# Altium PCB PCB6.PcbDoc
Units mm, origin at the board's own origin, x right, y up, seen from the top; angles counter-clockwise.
Board outline 26 x 20 mm, 2 copper layers (Top Layer, Bottom Layer); 9 components, 18 nets, 52 pads, 1 vias.
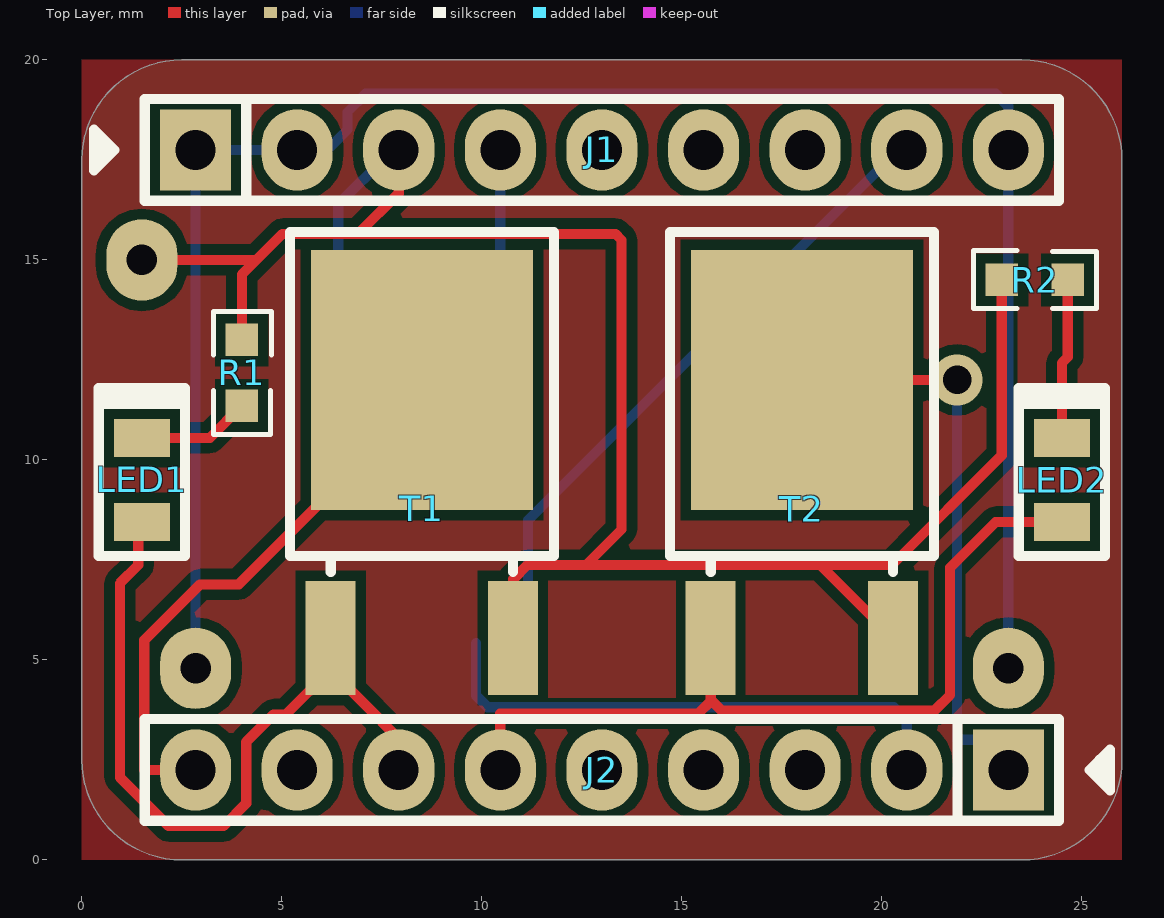
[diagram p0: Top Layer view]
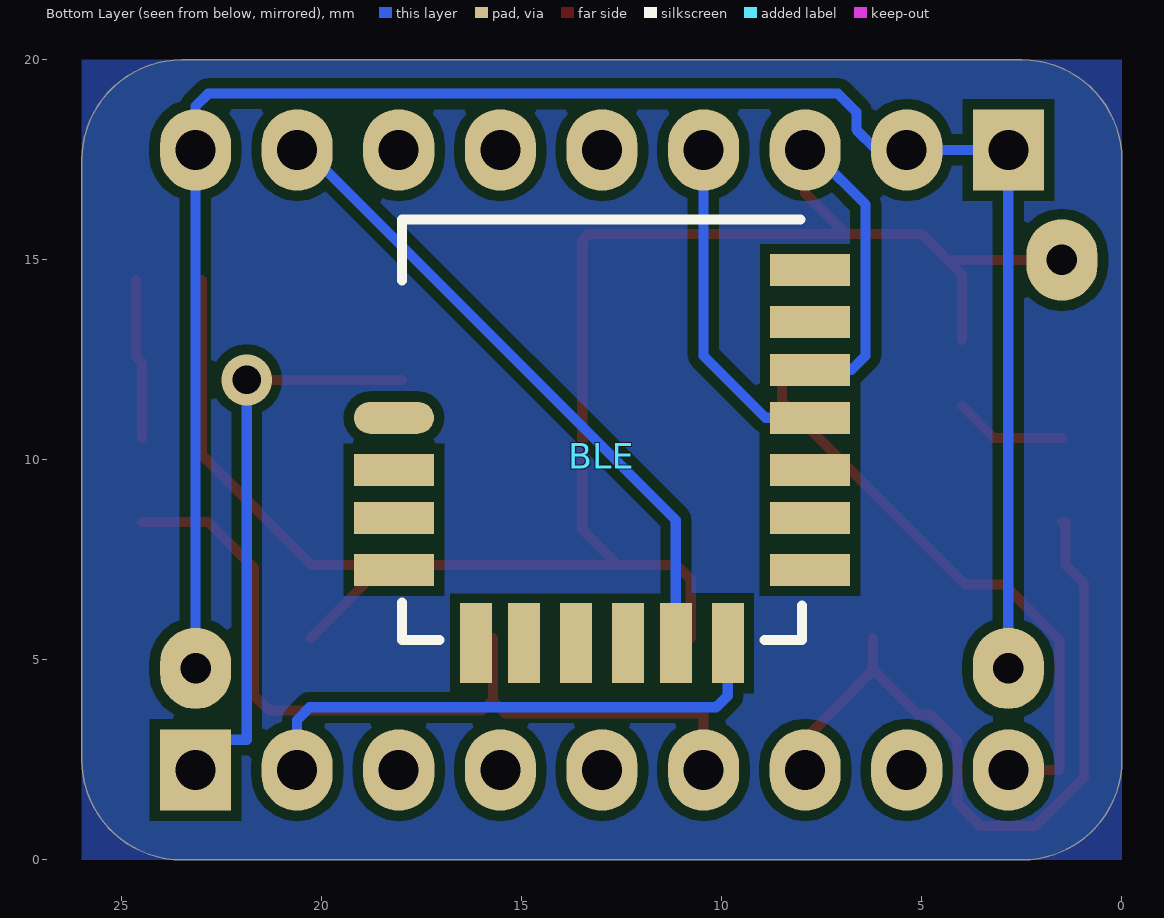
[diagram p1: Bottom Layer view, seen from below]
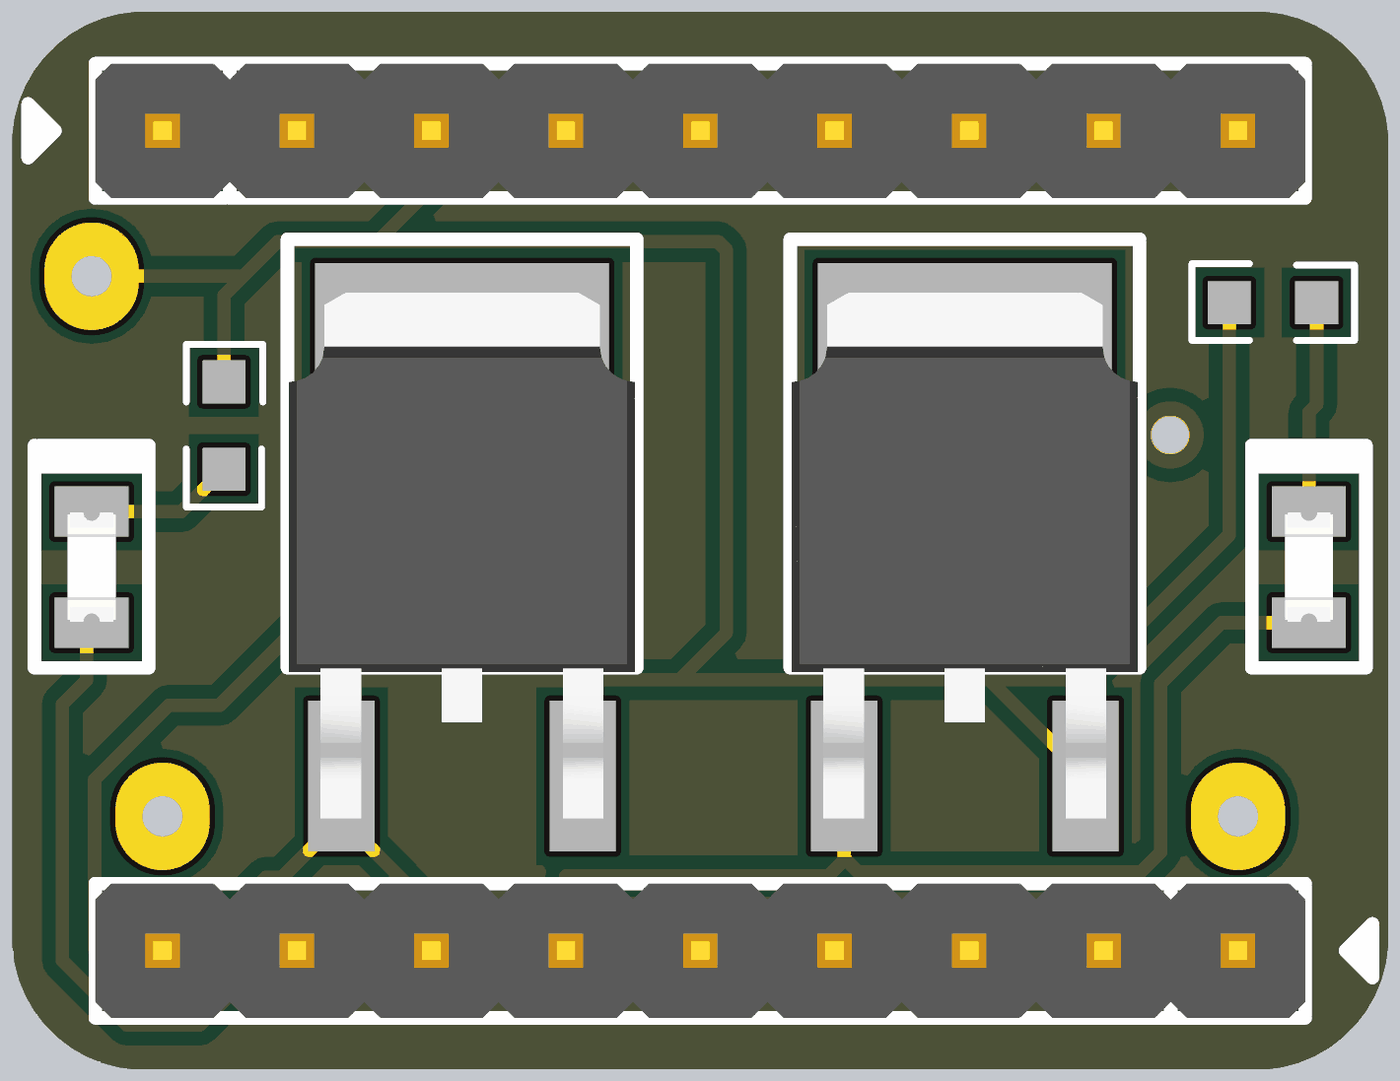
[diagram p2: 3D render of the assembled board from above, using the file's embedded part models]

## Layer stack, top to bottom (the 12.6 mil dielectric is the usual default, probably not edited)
Top Solder: solder mask 0.0102, Solder Resist, Dk 3.5
Top Layer: signal copper 0.0356
Dielectric 1: dielectric 0.32, FR-4, Dk 4.8
Bottom Layer: signal copper 0.0356
Bottom Solder: solder mask 0.0102, Solder Resist, Dk 3.5

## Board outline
0,2.5 ccw(c2.5,2.5) 2.5,0 23.5,0 ccw(c23.5,2.5) 26,2.5 26,17.5 ccw(c23.5,17.5) 23.5,20 2.5,20 ccw(c2.5,17.5) 0,17.5

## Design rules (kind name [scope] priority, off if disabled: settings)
Clearance [All] p1: gap=0.254
PolygonConnect [All] p1: connectstyle=Relief reliefconductorwidth=0.254 reliefentries=4 polygonreliefangle="90 Angle" airgapwidth=0.254
RoutingVias [All] p1: holewidth=0.711 width=1.27 viastyle="Through Hole" minholewidth=0.711 minwidth=1.27 maxholewidth=0.711 maxwidth=1.27
SolderMaskExpansion [All] p1: expansion=0.102
Width [All] p1: maxlimit=0.254 minlimit=0.254 preferedwidth=0.254
29 further rules are at their usual default settings.

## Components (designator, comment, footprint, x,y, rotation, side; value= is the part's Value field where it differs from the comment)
BLE "WH-BLE103" PCBComponent_1 18,5.5 r180 bottom
J1 "HDR1x9" PIN-9-2.54-1.0 13,17.75 r0 top
J2 "HDR1x9" PIN-9-2.54-1.0 13,2.25 r180 top
LED1 "LED" LED-0805 1.5,9.5 r90 top
LED2 "LED" LED-0805 24.5,9.5 r90 top
R1 "Res2" 0603 4,13 r270 top
R2 "Res2" 0603 23,14.5 r0 top
T1 "BT136S-600E" TO-252 8.5,12 r0 top
T2 "BT136S-600E" TO-252 18,12 r0 top

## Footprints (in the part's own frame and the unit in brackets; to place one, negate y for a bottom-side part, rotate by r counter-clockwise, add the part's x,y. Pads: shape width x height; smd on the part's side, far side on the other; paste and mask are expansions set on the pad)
0603 [mil]
  rect 32x32 smd: 1(-0.16,-0.01) 2(64.84,-0.01)
  silkscreen extent -28,-28 93,29
LED-0805 [mm] "LED, SMD, 0805"
  rect 0.95x1.4 smd: 1(-1.05,0) 2(1.05,0)
  silkscreen extent -1.9,-1.08 2.3,1.08, body extent -1.03,-0.46 1.03,0.45, height 0.85
PCBComponent_1 [mm]
  oval 2x0.8 smd: 1(-0.2,5.554)
  rect 2x0.8 smd: 2(-0.2,4.254) 3(-0.2,3.054) 4(-0.2,1.754) 11(10.2,1.754) 12(10.2,3.054) 13(10.2,4.254) 14(10.2,5.554) 15(10.2,6.754) 16(10.2,7.954) 17(10.2,9.254)
  rect 0.8x2 smd: 5(1.846,-0.082) 6(3.046,-0.082) 7(4.346,-0.082) 8(5.646,-0.082) 9(6.846,-0.082) 10(8.146,-0.082)
  silkscreen extent 0,0 10,10.51
PIN-9-2.54-1.0 [mil] "Pin Header"
  rect 70x80 hole 39.37: 1(-400,0)
  oval 70x80 hole 39.37: 2(-300,0) 3(-200,0) 4(-100,0) 5(0,0) 6(100,0) 7(200,0) 8(300,0) 9(400,0)
  silkscreen extent -500,-50 450,50, body extent -450,-50 450,50, height 398
TO-252 [mm] "TO-252, DPAK"
  rect 1.25x2.85 smd: 1(-2.28,-6.45) 3(2.28,-6.45)
  rect 5.55x6.5 smd: 4(0,0)
  silkscreen extent -3.3,-4.8 3.3,3.7, body extent -3.27,-7.25 3.27,2.69, height 2.41

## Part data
J1 J2: "Connector"
R1 R2: "Resistor"
T1 T2: "Triac"

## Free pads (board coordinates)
  oval 1.778x2.032 hole 0.762: 3(1.5,15) 3(2.84,4.79) 3(23.16,4.79)

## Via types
v1: diameter 1.27, hole 0.711, Top Layer to Bottom Layer, tented both sides, 1 vias

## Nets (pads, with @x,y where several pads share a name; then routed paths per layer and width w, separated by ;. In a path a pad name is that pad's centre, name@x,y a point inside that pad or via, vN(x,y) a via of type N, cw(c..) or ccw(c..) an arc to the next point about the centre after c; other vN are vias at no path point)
3.3V: BLE.14 J1.4 | length 8.4
  Bottom Layer w0.254: BLE.14 8.91,11.054 10.46,12.604 J1.4
5V: J1.1 J1.2 J1.9 | length 22.4
  Bottom Layer w0.254: J1.1 J1.2 6.131,17.75 6.639,18.258 6.639,18.7 7.096,19.157 22.844,19.157 23.16,18.841 J1.9
A1: J2.9 T1.4 | length 14.5
  Top Layer w0.254: J2.9 1.559,2.25 1.559,5.492 2.956,6.889 3.921,6.889 8.5,11.468 T1.4
A2: J2.1 T2.4 | length 14.9
  Top Layer w0.254: T2.4 v1(21.879,12)
  Bottom Layer w0.254: v1(21.879,12) 21.879,3.003 23.16,3.003 J2.1
CON0: J2.8
CON1: J2.7 LED1.1 T1.1 | length 19
  Top Layer w0.254: LED1.1 1.406,8.45 1.406,7.372 0.949,6.914 0.949,2.063 2.168,0.844 3.54,0.844 4.11,1.414 4.11,2.952 4.796,3.638 5.102,3.638 T1.1@6.22,4.755 ; T1.1 T1.1@6.22,4.755 ; J2.7 7.92,3.028 T1.1@6.22,4.755
CON2: J2.6 LED2.1 T2.1 | length 21.1
  Top Layer w0.254: J2.6 10.46,3.663 15.415,3.663 15.72,3.968 15.72,4.005 ; T2.1 15.72,4.005 ; LED2.1 22.844,8.45 21.701,7.307 21.701,4.12 21.32,3.739 15.986,3.739 15.72,4.005
CON3: J2.5
CON4: J1.5
CON5: J1.6
GND: BLE.15 J1.3 R1.1 R2.1 T1.3 T2.3 | length 52
  Top Layer w0.254: R1.1 4,14.636 5.016,15.652 6.904,15.652 ; J1.3 7.92,16.668 6.904,15.652 ; T1.3 10.78,7.016 11.136,7.372 12.602,7.372 ; T2.3 18.458,7.372 ; R2.1 22.996,10.114 20.253,7.372 18.458,7.372 ; 6.904,15.652 13.338,15.652 13.49,15.5 13.49,8.26 12.602,7.372 ; 12.602,7.372 18.458,7.372
  Bottom Layer w0.254: BLE.15 6.76,12.254 6.41,12.604 6.41,16.389 7.629,17.608 7.92,17.608 J1.3
NetLED1_2: LED1.2 R1.2 | length 2.8
  Top Layer w0.254: LED1.2 3.197,10.55 R1.2
NetLED2_2: LED2.2 R2.2 | length 4
  Top Layer w0.254: LED2.2 24.5,12.426 24.647,12.573 R2.2
RX: BLE.9 J1.8 | length 16.4
  Bottom Layer w0.254: BLE.9 11.154,8.499 20.406,17.75 J1.8
SCK: J1.7
SCL: J2.3
SDA: J2.4
TX: BLE.10 J2.2 | length 13.6
  Bottom Layer w0.254: BLE.10 9.854,4.105 10.144,3.816 20.304,3.816 20.62,3.5 J2.2
pads on no net: BLE.1 BLE.2 BLE.3 BLE.4 BLE.5 BLE.6 BLE.7 BLE.8 BLE.11 BLE.12 BLE.13 BLE.16 BLE.17
copper on no net: | length 29
  Top Layer w0.254: 1.5,15 4.364,15 4.5,15.136
  Bottom Layer w0.254: 2.84,4.79 2.84,17.75 ; 23.16,4.79 23.16,17.75

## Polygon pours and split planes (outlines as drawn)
no net on Top Layer "Top Layer-No Net" (solid, pour order 16): 0,20 26,20 26,0 0,0 0,20
no net on Bottom Layer "Top Layer-No Net" (solid, pour order 18): 0,20 26,20 26,0 0,0 0,20

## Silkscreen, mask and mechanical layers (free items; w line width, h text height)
Mechanical 1:
  the board outline again, w0.254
